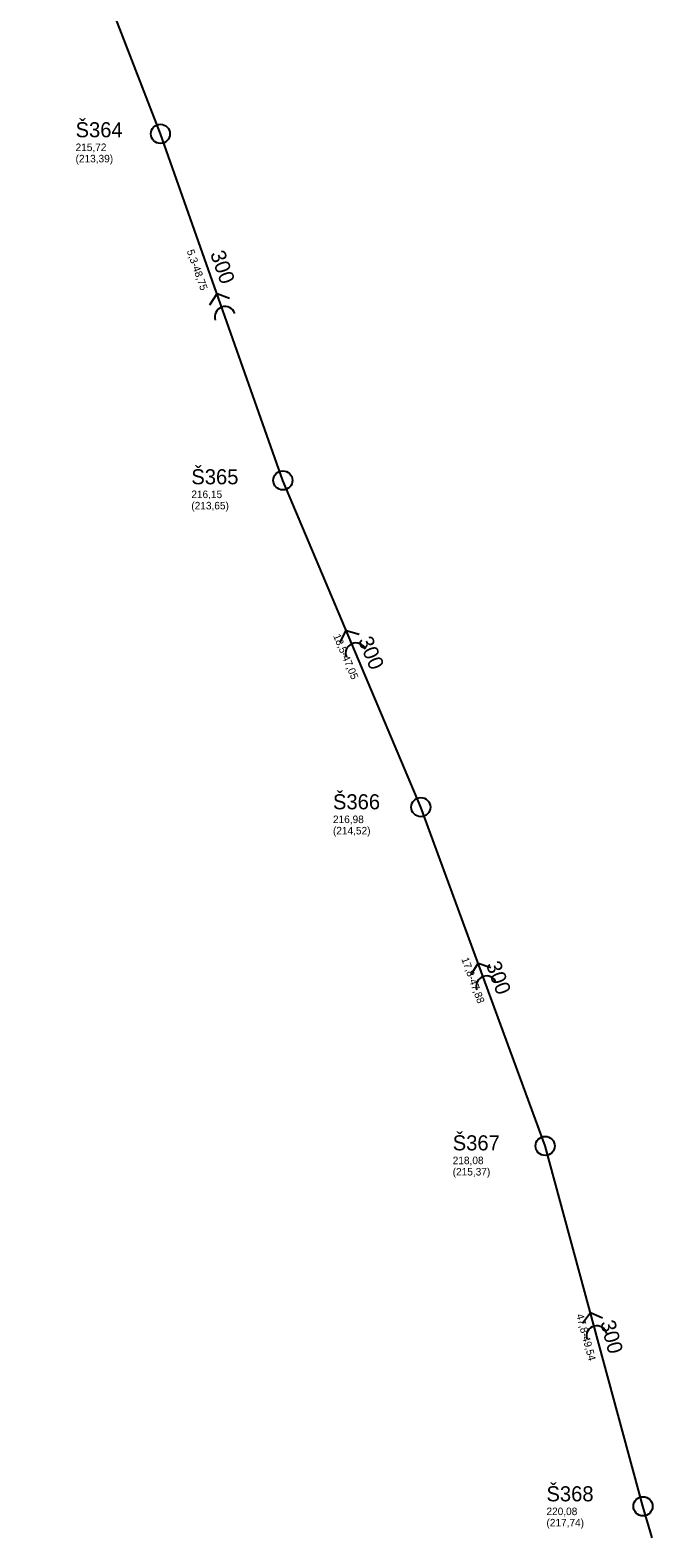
# Model space of a CAD drawing. Extents: x -574467 to -573663, y -1191209 to -1190406.
# Drawn here: x -573745.4 to -573662.5, y -1191208.7 to -1191008.6 of the extents above; entities that cross this region are included whole.
import ezdxf

# ---------------------------------------------------------------- set-up
doc = ezdxf.new("R2010")
doc.units = 0
for name, color, linetype in [('Vrstva 1', 7, 'Continuous'), ('Vrstva 15', 7, 'Continuous'), ('Vrstva 29', 7, 'Continuous'), ('Vrstva 41', 7, 'Continuous'), ('Vrstva 44', 7, 'Continuous'), ('Vrstva 45', 7, 'Continuous'), ('Vrstva 56', 7, 'Continuous'), ('Vrstva 57', 7, 'Continuous')]:
    doc.layers.add(name, color=color, linetype=linetype)

# ---------------------------------------------------------------- blocks, each defined once
blk = doc.blocks.new('100')
at = {"layer": 'Vrstva 1'}
blk.add_circle((0, 0), 1.27, dxfattribs=at)
blk = doc.blocks.new('86')
at = {"layer": 'Vrstva 1'}
blk.add_lwpolyline([(0.79, 1.37), (1.89, 0), (0.79, -1.38)], dxfattribs=at)
blk.add_arc((-1.37, 0), 1.37, 270, 90, dxfattribs=at)

msp = doc.modelspace()

# ---------------------------------------------------------------- linework, layer by layer
at = {"layer": 'Vrstva 15'}
for p, q in [((-573728.09, -1191022.4), (-573745.36, -1190977.75)), ((-573711.85, -1191068.37), (-573728.09, -1191022.4)), ((-573693.56, -1191111.72), (-573711.85, -1191068.37)), ((-573677.08, -1191156.67), (-573693.56, -1191111.72)), ((-573664.1, -1191204.48), (-573677.08, -1191156.67)), ((-573662.868, -1191208.664), (-573664.1, -1191204.48))]:
    msp.add_line(p, q, dxfattribs=at)

# ---------------------------------------------------------------- block references
at = {"layer": 'Vrstva 29'}
for p, xscale, yscale, rotation in [((-573728.09, -1191022.4), 0.9999999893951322, 0.9999999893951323, 109.99999905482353), ((-573711.85, -1191068.37), 0.999999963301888, 0.9999999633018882, 110.99999898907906), ((-573693.56, -1191111.72), 0.9999999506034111, 0.9999999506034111, 112.00000028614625), ((-573677.08, -1191156.67), 0.9999999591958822, 0.9999999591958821, 107.99999945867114), ((-573664.1, -1191204.48), 0.9999999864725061, 0.9999999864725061, 105.99999860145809)]:
    msp.add_blockref('100', p, dxfattribs=dict(at, xscale=xscale, yscale=yscale, rotation=rotation))
at = {"layer": 'Vrstva 41'}
for p, xscale, yscale, rotation in [((-573719.97, -1191045.385), 0.9999999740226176, 0.9999999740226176, 108.99999960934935), ((-573702.705, -1191090.045), 0.9999999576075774, 0.9999999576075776, 113.00000088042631), ((-573685.32, -1191134.195), 0.9999999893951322, 0.9999999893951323, 109.99999905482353), ((-573670.59, -1191180.575), 0.999999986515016, 0.9999999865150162, 105.00000012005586)]:
    msp.add_blockref('86', p, dxfattribs=dict(at, xscale=xscale, yscale=yscale, rotation=rotation))

# ---------------------------------------------------------------- texts
at = {"layer": 'Vrstva 44'}
for rotation, p in [(289.46, (-573721.525, -1191038.282)), (292.88, (-573701.929, -1191089.575)), (290.13, (-573684.948, -1191132.592)), (285.19, (-573669.79, -1191180.096))]:
    msp.add_text('300', height=2, rotation=rotation, dxfattribs=at).set_placement(p)
at = {"layer": 'Vrstva 45'}
for s, rotation, p in [('5,3-48,75', 289.46, (-573724.613, -1191037.943)), ('18,5-47,05', 292.88, (-573705.203, -1191088.999)), ('17,8-47,88', 290.13, (-573688.2, -1191131.862)), ('47,8-49,54', 285.19, (-573672.966, -1191179.088))]:
    msp.add_text(s, height=1, rotation=rotation, dxfattribs=at).set_placement(p)
at = {"layer": 'Vrstva 56'}
for s, p in [('215,72 ', (-573739.34, -1191024.68)), ('(213,39)', (-573739.34, -1191026.18)), ('216,15 ', (-573723.99, -1191070.72)), ('(213,65)', (-573723.99, -1191072.22)), ('216,98 ', (-573705.21, -1191113.84)), ('(214,52)', (-573705.21, -1191115.34)), ('218,08 ', (-573689.33, -1191159.09)), ('(215,37)', (-573689.33, -1191160.59)), ('220,08 ', (-573676.9, -1191205.65)), ('(217,74)', (-573676.9, -1191207.15))]:
    msp.add_text(s, height=1, dxfattribs=at).set_placement(p)
at = {"layer": 'Vrstva 57'}
for s, p in [('Š364', (-573739.34, -1191022.85)), ('Š365', (-573723.99, -1191068.89)), ('Š366', (-573705.21, -1191112.01)), ('Š367', (-573689.33, -1191157.26)), ('Š368', (-573676.9, -1191203.82))]:
    msp.add_text(s, height=2, dxfattribs=at).set_placement(p)

doc.saveas('drawing.dxf')
